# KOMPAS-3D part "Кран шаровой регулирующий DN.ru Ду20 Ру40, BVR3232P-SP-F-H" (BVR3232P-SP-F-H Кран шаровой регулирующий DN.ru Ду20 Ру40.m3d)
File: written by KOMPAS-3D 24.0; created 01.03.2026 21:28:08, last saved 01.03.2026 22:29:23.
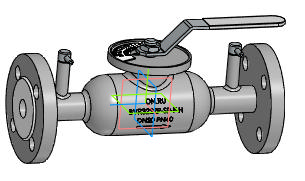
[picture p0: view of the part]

Document properties: Автор: Максим; Полное имя файла: BVR3232P-SP-F-H  - Кран шаровой регулирующий DN.ru  Ду20 Ру40.cdw

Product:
- Body: Тело 1  | qty 1
    Масса: 4.807827
- Part/product: Кран шаровой регулирующий DN.ru Ду20 Ру40  | designation BVR3232P-SP-F-H
    Масса: 3.5
    Раздел спецификации: Прочие изделия
    Форматы листов документа: A2
    Примечание: D160-69418

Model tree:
1. Операция без истории:1

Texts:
  BVR3232P-SP-F-H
